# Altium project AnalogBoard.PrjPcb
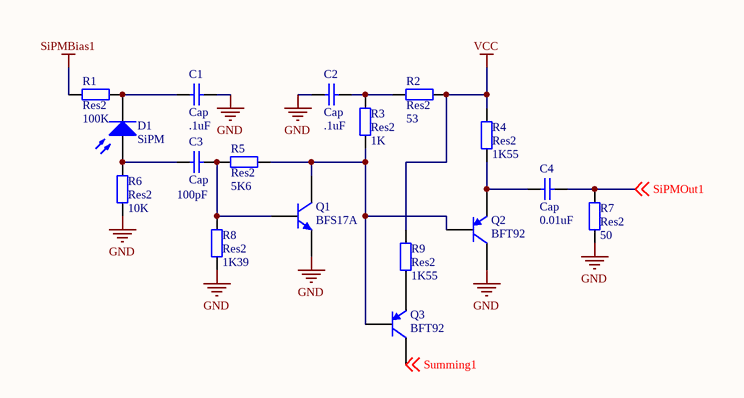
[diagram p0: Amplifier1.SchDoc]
2 sheets, 21 parts. Net scope: global (net labels, ports and power ports of the same name join across sheets).
Board file: AnalogBoardPCB.PcbDoc
Sheets:
  Amplifier1.SchDoc
  Summer.SchDoc

## Sheet Amplifier1.SchDoc
size A

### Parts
(Parts that share a designator on the sheet are numbered #1, #2 ... from top to bottom, then left to right.)
C1  Cap  value .1uF  [0402]
C2  Cap  value .1uF  [0402]
C3  Cap  value 100pF  [0402]
C4  Cap  value 0.01uF  [0402]
D1  SiPM  [Photonique SiPM]
Q1#1  BFS17A  [SOT23_N]
Q2  BFT92  [SOT23_N]
Q3  BFT92  [SOT23_N]
R1#1  Res2  value 100K  [1005[0402]]
R2#1  Res2  value 53  [1005[0402]]
R3#1  Res2  value 1K  [1005[0402]]
R4  Res2  value 1K55  [1005[0402]]
R5  Res2  value 5K6  [1005[0402]]
R6  Res2  value 10K  [1005[0402]]
R7  Res2  value 50  [1005[0402]]
R8  Res2  value 1K39  [1005[0402]]
R9  Res2  value 1K55  [1005[0402]]

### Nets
GND: C1.2 C2.1 Q1#1.2(E) Q2.3(C) R6.1 R7.1 R8.1
SiPMBias1: R1#1.1
VCC: R2#1.2 R4.2 R9.2
SiPMOut1: C4.2 R7.2 ; off-sheet SiPMOut1
Summing1: Q3.3(C) ; off-sheet Summing1
NetC1_1: C1.1 D1.2(K) R1#1.2
NetC2_2: C2.2 R2#1.1 R3#1.2
NetC3_1: C3.1 D1.1(A) R6.2
NetC3_2: C3.2 Q1#1.1(B) R5.1 R8.2
NetC4_1: C4.1 Q2.2(E) R4.1
NetQ1#1_3: Q1#1.3(C) Q2.1(B) Q3.1(B) R3#1.1 R5.2
NetQ3_2: Q3.2(E) R9.1

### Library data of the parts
C1-C4 = Cap: Capacitor
D1 = Photo Sen: Photosensitive Diode
Q1#1 = BFS17A: NPN 3 GHz Wideband Transistor
Q2 Q3 = BFT92: PNP 5 GHz Wideband Transistor
R1#1 R2#1 R3#1 R4-R9 = Res2: Resistor

## Sheet Summer.SchDoc
size A
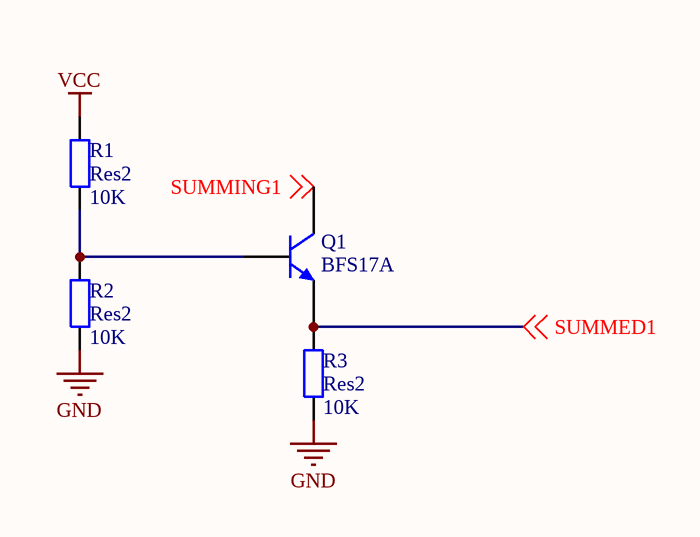
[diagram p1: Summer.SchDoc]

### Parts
(Parts that share a designator on the sheet are numbered #1, #2 ... from top to bottom, then left to right.)
Q1#2  BFS17A  [SOT23_N]
R1#2  Res2  value 10K  [1005[0402]]
R2#2  Res2  value 10K  [1005[0402]]
R3#2  Res2  value 10K  [1005[0402]]

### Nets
GND: R2#2.1 R3#2.1
VCC: R1#2.2
SUMMED1: Q1#2.2(E) R3#2.2 ; off-sheet SUMMED1
Summing1: Q1#2.3(C) ; off-sheet SUMMING1
NetQ1#2_1: Q1#2.1(B) R1#2.1 R2#2.2

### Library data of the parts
Q1#2 = BFS17A: NPN 3 GHz Wideband Transistor
R1#2 R2#2 R3#2 = Res2: Resistor

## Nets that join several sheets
GND: Amplifier1 (7 pins), Summer (R2#2.1 R3#2.1)
VCC: Amplifier1 (R2#1.2 R4.2 R9.2), Summer (R1#2.2)
Summing1: Amplifier1 (Q3.3), Summer (Q1#2.3)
